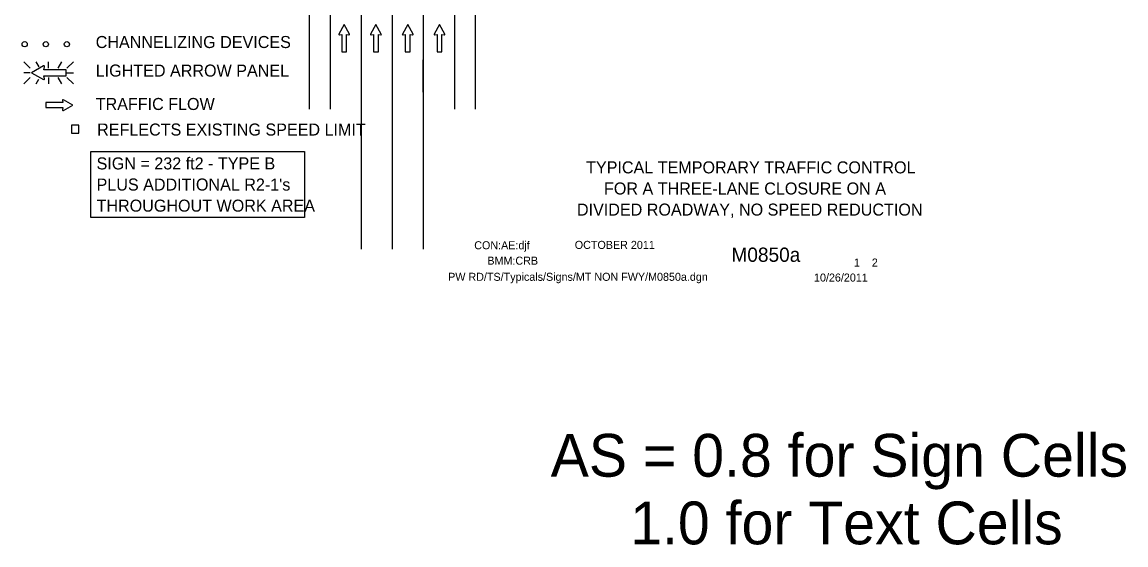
# Model space of a CAD drawing. Extents: x 16742 to 18475, y 7016 to 8203.
# Drawn here: x 16742 to 17594, y 7016 to 7420 of the extents above; entities that cross this region are included whole.
import ezdxf

# ---------------------------------------------------------------- set-up
doc = ezdxf.new("R2010")
doc.units = 0
for name, color, linetype in [('ALI_LEGAL_EX', 7, 'Continuous'), ('BORDER', 7, 'Continuous'), ('BORDER_SIGNAL_WO', 7, 'Continuous'), ('MT_SCRATCH_LEVEL_E', 7, 'Continuous'), ('PAVT_EDGE_EX', 7, 'Continuous'), ('TRAFFIC_SIGNS_PR', 7, 'Continuous'), ('TYPICAL_TEXT_DIMEN_EX', 7, 'Continuous')]:
    doc.layers.add(name, color=color, linetype=linetype)

msp = doc.modelspace()

# ---------------------------------------------------------------- linework, layer by layer
at = {"layer": 'ALI_LEGAL_EX'}
for p, q in [((17003.37, 8174.11), (17003.37, 7344.93)), ((17027.37, 8174.11), (17027.37, 7344.93)), ((17051.37, 8174.11), (17051.37, 7344.93)), ((17051.37, 8174.11), (17051.37, 7344.93)), ((17003.37, 8073.55), (17003.37, 7244.36)), ((17027.37, 8073.55), (17027.37, 7244.36)), ((17051.37, 8073.55), (17051.37, 7244.36)), ((17051.37, 8073.55), (17051.37, 7244.36))]:
    msp.add_line(p, q, dxfattribs=at)
for points in [[(17003.37, 7390.64), (17003.37, 7365.64)], [(17027.37, 7390.64), (17027.37, 7365.64)], [(17051.37, 7365.64), (17051.37, 7390.64)], [(17051.37, 7390.64), (17051.37, 7365.64)]]:
    msp.add_lwpolyline(points, dxfattribs=at)
at = {"layer": 'MT_SCRATCH_LEVEL_E'}
for p, q in [((16990.28, 7417.75), (16986.16, 7410.51)), ((16990.28, 7417.75), (16986.16, 7410.51)), ((16994.42, 7410.51), (16990.28, 7417.75)), ((16994.42, 7410.51), (16990.28, 7417.75)), ((17014.8, 7417.75), (17010.69, 7410.51)), ((17014.8, 7417.75), (17010.69, 7410.51)), ((17018.95, 7410.51), (17014.8, 7417.75)), ((17018.95, 7410.51), (17014.8, 7417.75)), ((17039.33, 7417.75), (17035.22, 7410.51)), ((17039.33, 7417.75), (17035.22, 7410.51)), ((17043.48, 7410.51), (17039.33, 7417.75)), ((17043.48, 7410.51), (17039.33, 7417.75)), ((17063.89, 7417.75), (17059.78, 7410.51)), ((17063.89, 7417.75), (17059.78, 7410.51)), ((17068.04, 7410.51), (17063.89, 7417.75)), ((17068.04, 7410.51), (17063.89, 7417.75)), ((16986.65, 7409.83), (16988.42, 7410.14)), ((16986.65, 7409.83), (16988.42, 7410.14)), ((16988.42, 7410.14), (16988.42, 7396.89)), ((16988.42, 7410.14), (16988.42, 7396.89)), ((16992.17, 7396.89), (16992.17, 7410.14)), ((16992.17, 7410.14), (16993.94, 7409.83)), ((16992.17, 7396.89), (16992.17, 7410.14)), ((16992.17, 7410.14), (16993.94, 7409.83)), ((17011.17, 7409.83), (17012.95, 7410.14)), ((17011.17, 7409.83), (17012.95, 7410.14)), ((17012.95, 7410.14), (17012.95, 7396.89)), ((17012.95, 7410.14), (17012.95, 7396.89)), ((17016.69, 7396.89), (17016.69, 7410.14)), ((17016.69, 7410.14), (17018.47, 7409.83)), ((17016.69, 7396.89), (17016.69, 7410.14)), ((17016.69, 7410.14), (17018.47, 7409.83)), ((17035.7, 7409.83), (17037.48, 7410.14)), ((17035.7, 7409.83), (17037.48, 7410.14)), ((17037.48, 7410.14), (17037.48, 7396.89)), ((17037.48, 7410.14), (17037.48, 7396.89)), ((17041.22, 7396.89), (17041.22, 7410.14)), ((17041.22, 7410.14), (17043, 7409.83)), ((17041.22, 7396.89), (17041.22, 7410.14)), ((17041.22, 7410.14), (17043, 7409.83)), ((17060.26, 7409.83), (17062.04, 7410.14)), ((17060.26, 7409.83), (17062.04, 7410.14)), ((17062.04, 7410.14), (17062.04, 7396.89)), ((17062.04, 7410.14), (17062.04, 7396.89)), ((17065.78, 7396.89), (17065.78, 7410.14)), ((17065.78, 7410.14), (17067.56, 7409.83)), ((17065.78, 7396.89), (17065.78, 7410.14)), ((17065.78, 7410.14), (17067.56, 7409.83)), ((16988.42, 7396.89), (16992.17, 7396.89)), ((16988.42, 7396.89), (16992.17, 7396.89)), ((17012.95, 7396.89), (17016.69, 7396.89)), ((17012.95, 7396.89), (17016.69, 7396.89)), ((17037.48, 7396.89), (17041.22, 7396.89)), ((17037.48, 7396.89), (17041.22, 7396.89)), ((17062.04, 7396.89), (17065.78, 7396.89)), ((17062.04, 7396.89), (17065.78, 7396.89)), ((16773.2, 7357.55), (16759.94, 7357.55)), ((16759.94, 7357.55), (16759.94, 7353.81)), ((16773.2, 7357.55), (16759.94, 7357.55)), ((16759.94, 7357.55), (16759.94, 7353.81)), ((16759.94, 7353.81), (16773.2, 7353.81)), ((16759.94, 7353.81), (16773.2, 7353.81)), ((16772.88, 7359.33), (16773.2, 7357.55)), ((16772.88, 7359.33), (16773.2, 7357.55)), ((16773.2, 7353.81), (16772.88, 7352.03)), ((16773.2, 7353.81), (16772.88, 7352.03)), ((16780.81, 7355.7), (16773.57, 7359.81)), ((16780.81, 7355.7), (16773.57, 7359.81)), ((16773.57, 7351.55), (16780.81, 7355.7)), ((16773.57, 7351.55), (16780.81, 7355.7))]:
    msp.add_line(p, q, dxfattribs=at)
for centre, start, end in [((16986.57, 7410.29), 150.42484, 279.96381), ((16986.57, 7410.29), 150.42484, 279.96381), ((16994.01, 7410.29), 260.03619, 29.77312), ((16994.01, 7410.29), 260.03619, 29.77312), ((17011.1, 7410.29), 150.42484, 279.96381), ((17011.1, 7410.29), 150.42484, 279.96381), ((17018.54, 7410.29), 260.03619, 29.77312), ((17018.54, 7410.29), 260.03619, 29.77312), ((17035.63, 7410.29), 150.42484, 279.96381), ((17035.63, 7410.29), 150.42484, 279.96381), ((17043.07, 7410.29), 260.03619, 29.77312), ((17043.07, 7410.29), 260.03619, 29.77312), ((17060.19, 7410.29), 150.42484, 279.96381), ((17060.19, 7410.29), 150.42484, 279.96381), ((17067.63, 7410.29), 260.03619, 29.77312), ((17067.63, 7410.29), 260.03619, 29.77312), ((16773.34, 7359.4), 60.42484, 189.96381), ((16773.34, 7359.4), 60.42484, 189.96381), ((16773.34, 7351.96), 170.03619, 299.77312), ((16773.34, 7351.96), 170.03619, 299.77312)]:
    msp.add_arc(centre, 0.463, start, end, dxfattribs=at)
at = {"layer": 'PAVT_EDGE_EX'}
for p, q in [((16963.37, 8203.06), (16963.37, 7352.47)), ((16979.37, 8203.06), (16979.37, 7352.47)), ((17075.37, 8203.06), (17075.37, 7352.47)), ((17091.37, 8203.06), (17091.37, 7352.47))]:
    msp.add_line(p, q, dxfattribs=at)
at = {"layer": 'TRAFFIC_SIGNS_PR'}
for p, q in [((16743.12, 7389.09), (16748.05, 7384.15)), ((16754.88, 7385.27), (16752.67, 7389.09)), ((16762.2, 7384.15), (16762.2, 7389.09)), ((16769.44, 7384.15), (16772.28, 7389.09)), ((16776.35, 7384.15), (16781.28, 7389.09)), ((16748.05, 7380.6), (16743.12, 7380.6)), ((16776.35, 7380.6), (16781.28, 7380.6)), ((16743.12, 7372.11), (16748.05, 7377.04)), ((16752.63, 7372.11), (16754.74, 7375.77)), ((16762.2, 7377.04), (16762.2, 7372.11)), ((16772.33, 7372.11), (16769.48, 7377.04)), ((16776.35, 7377.04), (16781.28, 7372.11))]:
    msp.add_line(p, q, dxfattribs=at)
for points in [[(16758.13, 7385.87), (16748.84, 7380.6), (16758.13, 7375.28)], [(16759, 7375.9), (16758.6, 7378.17), (16775.62, 7378.17), (16775.62, 7382.97), (16758.6, 7382.97), (16759.01, 7385.25)]]:
    msp.add_lwpolyline(points, dxfattribs=at)
msp.add_lwpolyline([(16779.78, 7333.95), (16785.38, 7333.95), (16785.38, 7340.12), (16779.78, 7340.12)], close=True, dxfattribs=at)
for centre in [(16743.68, 7402.63), (16759.98, 7402.63), (16776.28, 7402.63)]:
    msp.add_circle(centre, 2, dxfattribs=at)
for centre, radius, start, end in [((16758.42, 7385.35), 0.598, 350.73078, 118.89165), ((16758.41, 7375.8), 0.597, 241.48329, 9.95933)]:
    msp.add_arc(centre, radius, start, end, dxfattribs=at)
at = {"layer": 'TYPICAL_TEXT_DIMEN_EX'}
msp.add_lwpolyline([(16794.75, 7319.69), (16959.63, 7319.69), (16959.63, 7268.75), (16794.75, 7268.75)], close=True, dxfattribs=at)

# ---------------------------------------------------------------- texts
at = {"layer": 'BORDER'}
for s, p in [('TYPICAL TEMPORARY TRAFFIC CONTROL', (17177.02, 7302.9)), ('FOR A THREE-LANE CLOSURE ON A', (17190.84, 7286.6)), ('DIVIDED ROADWAY, NO SPEED REDUCTION', (17169.96, 7270.3))]:
    msp.add_text(s, height=9.3, dxfattribs=at).set_placement(p)
at = {"layer": 'BORDER_SIGNAL_WO'}
for s, height, p in [('CON:AE:djf', 6.2, (17090.69, 7244.31)), ('    OCTOBER 2011    ', 6.2, (17159.08, 7244.59)), ('    M0850a   ', 11, (17272.86, 7234.63)), ('BMM:CRB   ', 6.2, (17100.81, 7232.42)), (' 1    2 ', 6.2, (17381.45, 7230.95)), ('PW RD/TS/Typicals/Signs/MT NON FWY/M0850a.dgn    ', 6.2, (17070.55, 7219.96)), ('10/26/2011    ', 6.2, (17352.93, 7219.38)), ('AS = 0.8 for Sign Cells', 33.0301, (17149.69, 7068.73)), ('     1.0 for Text Cells', 33.0301, (17149.69, 7016.5))]:
    msp.add_text(s, height=height, dxfattribs=at).set_placement(p)
at = {"layer": 'TYPICAL_TEXT_DIMEN_EX'}
for s, p in [('CHANNELIZING DEVICES', (16798.52, 7399.69)), ('LIGHTED ARROW PANEL', (16798.52, 7377.64)), ('TRAFFIC FLOW', (16798.52, 7351.84)), ('REFLECTS EXISTING SPEED LIMIT', (16799.61, 7332.11)), ('SIGN = 232 ft2 - TYPE B', (16799.18, 7305.95)), ("PLUS ADDITIONAL R2-1's", (16799.18, 7289.65)), ('THROUGHOUT WORK AREA', (16799.18, 7273.35))]:
    msp.add_text(s, height=9.3, dxfattribs=at).set_placement(p)

doc.saveas('drawing.dxf')
